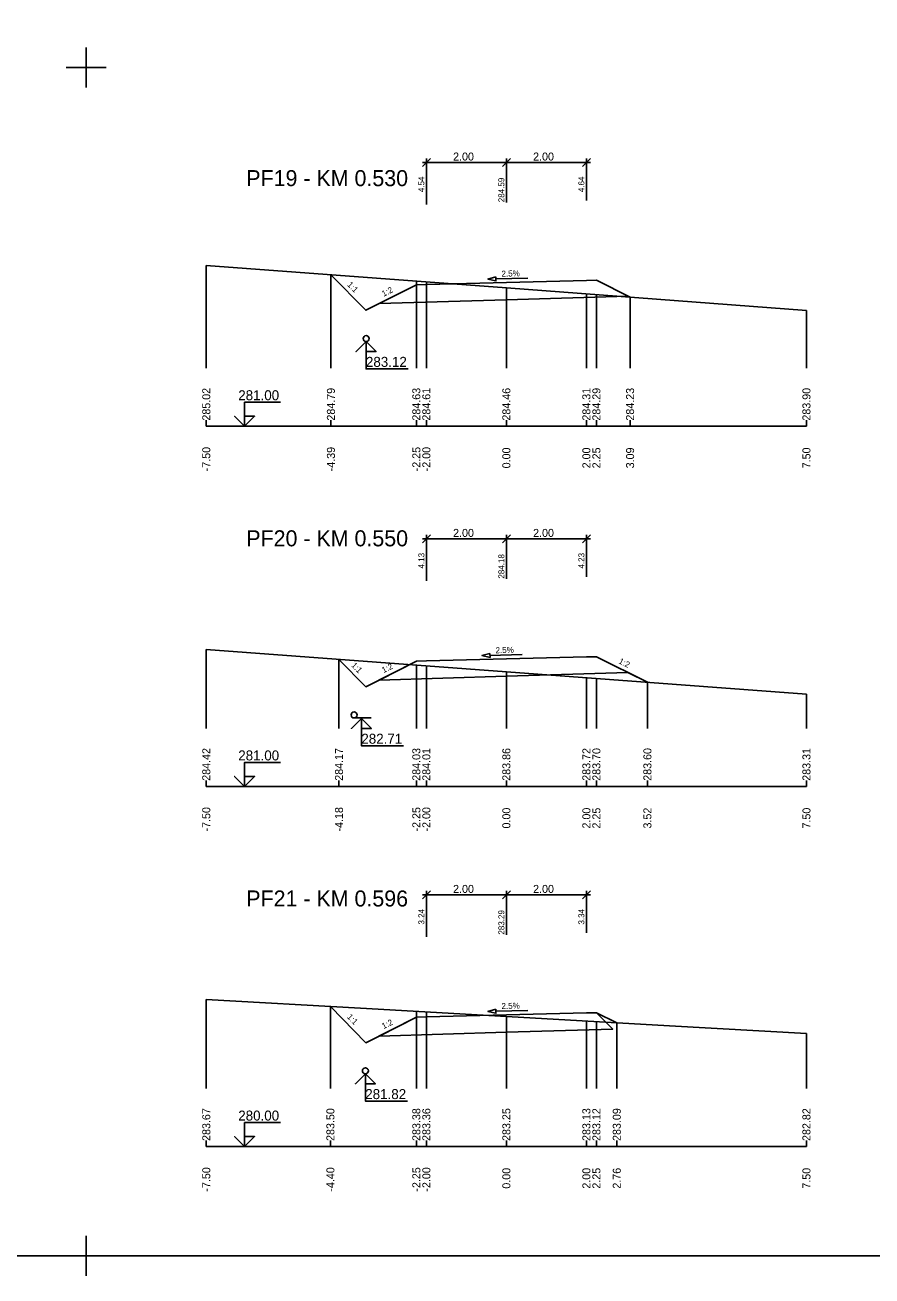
# Model space of a CAD drawing. Extents: x -5 to 1895, y -2 to 602.
# Drawn here: x 1244.7 to 1456.4, y -2.3 to 310.3 of the extents above; entities that cross this region are included whole.
import ezdxf

# ---------------------------------------------------------------- set-up
doc = ezdxf.new("R2010")
doc.units = 0
for name, color, linetype in [('KOTA', 7, 'Continuous'), ('KOTA_DELKY', 7, 'Continuous'), ('KOTA_DELKY_CONT', 7, 'Continuous'), ('KRIZENI', 7, 'Continuous'), ('NS_TELESO_VOZOVKY', 7, 'Continuous'), ('NS_V_PF', 7, 'Continuous'), ('REZY_PF_PUVODNI', 7, 'Continuous'), ('SESTAVY_REZU_PF', 7, 'Continuous'), ('SKLON', 7, 'Continuous'), ('SVK', 7, 'Continuous')]:
    doc.layers.add(name, color=color, linetype=linetype)

msp = doc.modelspace()

# ---------------------------------------------------------------- linework, layer by layer
for p, q in [((1260, 304.67), (1260, 294.67)), ((1260, 304.67), (1260, 294.67)), ((1260, 304.67), (1260, 294.67)), ((1260, 304.67), (1260, 294.67)), ((1260, 304.67), (1260, 294.67)), ((1260, 304.67), (1260, 294.67)), ((1260, 304.67), (1260, 294.67)), ((1260, 304.67), (1260, 294.67)), ((1260, 304.67), (1260, 294.67)), ((1260, 304.67), (1260, 294.67)), ((1260, 304.67), (1260, 294.67)), ((1260, 304.67), (1260, 294.67)), ((1260, 304.67), (1260, 294.67)), ((1260, 304.67), (1260, 294.67)), ((1260, 304.67), (1260, 294.67)), ((1260, 304.67), (1260, 294.67)), ((1260, 304.67), (1260, 294.67)), ((1260, 304.67), (1260, 294.67)), ((1260, 304.67), (1260, 294.67)), ((1260, 304.67), (1260, 294.67)), ((1260, 304.67), (1260, 294.67)), ((1260, 304.67), (1260, 294.67)), ((1260, 304.67), (1260, 294.67)), ((1260, 304.67), (1260, 294.67)), ((1260, 304.67), (1260, 294.67)), ((1260, 304.67), (1260, 294.67)), ((1260, 304.67), (1260, 294.67)), ((1260, 304.67), (1260, 294.67)), ((1260, 304.67), (1260, 294.67)), ((1260, 304.67), (1260, 294.67)), ((1260, 304.67), (1260, 294.67)), ((1260, 304.67), (1260, 294.67)), ((1260, 304.67), (1260, 294.67)), ((1260, 304.67), (1260, 294.67)), ((1260, 304.67), (1260, 294.67)), ((1260, 304.67), (1260, 294.67)), ((1260, 304.67), (1260, 294.67)), ((1260, 304.67), (1260, 294.67)), ((1260, 304.67), (1260, 294.67)), ((1260, 304.67), (1260, 294.67)), ((1260, 304.67), (1260, 294.67)), ((1260, 304.67), (1260, 294.67)), ((1260, 304.67), (1260, 294.67)), ((1260, 304.67), (1260, 294.67)), ((1260, 304.67), (1260, 294.67)), ((1260, 304.67), (1260, 294.67)), ((1260, 304.67), (1260, 294.67)), ((1260, 304.67), (1260, 294.67)), ((1260, 304.67), (1260, 294.67)), ((1260, 304.67), (1260, 294.67)), ((1260, 304.67), (1260, 294.67)), ((1260, 304.67), (1260, 294.67)), ((1260, 304.67), (1260, 294.67)), ((1260, 304.67), (1260, 294.67)), ((1265, 299.67), (1255, 299.67)), ((1265, 299.67), (1255, 299.67)), ((1265, 299.67), (1255, 299.67)), ((1265, 299.67), (1255, 299.67)), ((1265, 299.67), (1255, 299.67)), ((1265, 299.67), (1255, 299.67)), ((1265, 299.67), (1255, 299.67)), ((1265, 299.67), (1255, 299.67)), ((1265, 299.67), (1255, 299.67)), ((1265, 299.67), (1255, 299.67)), ((1265, 299.67), (1255, 299.67)), ((1265, 299.67), (1255, 299.67)), ((1265, 299.67), (1255, 299.67)), ((1265, 299.67), (1255, 299.67)), ((1265, 299.67), (1255, 299.67)), ((1265, 299.67), (1255, 299.67)), ((1265, 299.67), (1255, 299.67)), ((1265, 299.67), (1255, 299.67)), ((1265, 299.67), (1255, 299.67)), ((1265, 299.67), (1255, 299.67)), ((1265, 299.67), (1255, 299.67)), ((1265, 299.67), (1255, 299.67)), ((1265, 299.67), (1255, 299.67)), ((1265, 299.67), (1255, 299.67)), ((1265, 299.67), (1255, 299.67)), ((1265, 299.67), (1255, 299.67)), ((1265, 299.67), (1255, 299.67)), ((1265, 299.67), (1255, 299.67)), ((1265, 299.67), (1255, 299.67)), ((1265, 299.67), (1255, 299.67)), ((1265, 299.67), (1255, 299.67)), ((1265, 299.67), (1255, 299.67)), ((1265, 299.67), (1255, 299.67)), ((1265, 299.67), (1255, 299.67)), ((1265, 299.67), (1255, 299.67)), ((1265, 299.67), (1255, 299.67)), ((1265, 299.67), (1255, 299.67)), ((1265, 299.67), (1255, 299.67)), ((1265, 299.67), (1255, 299.67)), ((1265, 299.67), (1255, 299.67)), ((1265, 299.67), (1255, 299.67)), ((1265, 299.67), (1255, 299.67)), ((1265, 299.67), (1255, 299.67)), ((1265, 299.67), (1255, 299.67)), ((1265, 299.67), (1255, 299.67)), ((1265, 299.67), (1255, 299.67)), ((1265, 299.67), (1255, 299.67)), ((1265, 299.67), (1255, 299.67)), ((1265, 299.67), (1255, 299.67)), ((1265, 299.67), (1255, 299.67)), ((1265, 299.67), (1255, 299.67)), ((1265, 299.67), (1255, 299.67)), ((1265, 299.67), (1255, 299.67)), ((1265, 299.67), (1255, 299.67)), ((1260, 7.67), (1260, -2.33)), ((1260, 7.67), (1260, -2.33)), ((1260, 7.67), (1260, -2.33)), ((1260, 7.67), (1260, -2.33)), ((1260, 7.67), (1260, -2.33)), ((1260, 7.67), (1260, -2.33)), ((1260, 7.67), (1260, -2.33)), ((1260, 7.67), (1260, -2.33)), ((1260, 7.67), (1260, -2.33)), ((1260, 7.67), (1260, -2.33)), ((1260, 7.67), (1260, -2.33)), ((1260, 7.67), (1260, -2.33)), ((1265, 2.67), (1255, 2.67)), ((1265, 2.67), (1255, 2.67)), ((1265, 2.67), (1255, 2.67)), ((1265, 2.67), (1255, 2.67)), ((1265, 2.67), (1255, 2.67)), ((1265, 2.67), (1255, 2.67)), ((1265, 2.67), (1255, 2.67)), ((1265, 2.67), (1255, 2.67)), ((1265, 2.67), (1255, 2.67)), ((1265, 2.67), (1255, 2.67)), ((1265, 2.67), (1255, 2.67)), ((1265, 2.67), (1255, 2.67))]:
    msp.add_line(p, q)
msp.add_lwpolyline([(0, 596.67), (1890, 596.67), (1890, 2.67), (0, 2.67)], close=True)
at = {"layer": 'KOTA'}
for points in [[(1329.95, 231.16), (1327.45, 228.66), (1329.95, 231.16), (1329.95, 224.34), (1340.49, 224.34)], [(1329.95, 231.16), (1332.45, 228.66), (1329.95, 228.66), (1329.95, 231.16)], [(1329.95, 231.16), (1332.45, 228.66), (1329.95, 228.66)], [(1299.57, 210), (1297.07, 212.5), (1299.57, 210), (1299.57, 216), (1308.57, 216)], [(1299.57, 210), (1302.07, 212.5), (1299.57, 212.5), (1299.57, 210)], [(1299.57, 210), (1302.07, 212.5), (1299.57, 212.5)], [(1328.79, 136.99), (1326.29, 134.49), (1328.79, 136.99), (1328.79, 130.17), (1339.33, 130.17)], [(1326.95, 137.11), (1331.22, 137.11)], [(1328.79, 136.99), (1331.29, 134.49), (1328.79, 134.49), (1328.79, 136.99)], [(1328.79, 136.99), (1331.29, 134.49), (1328.79, 134.49)], [(1299.57, 120), (1297.07, 122.5), (1299.57, 120), (1299.57, 126), (1308.57, 126)], [(1299.57, 120), (1302.07, 122.5), (1299.57, 122.5), (1299.57, 120)], [(1299.57, 120), (1302.07, 122.5), (1299.57, 122.5)], [(1329.77, 48.19), (1327.27, 45.69), (1329.77, 48.19), (1329.77, 41.37), (1340.31, 41.37)], [(1329.77, 48.19), (1332.27, 45.69), (1329.77, 45.69), (1329.77, 48.19)], [(1329.77, 48.19), (1332.27, 45.69), (1329.77, 45.69)], [(1299.57, 30), (1297.07, 32.5), (1299.57, 30), (1299.57, 36), (1308.57, 36)], [(1299.57, 30), (1302.07, 32.5), (1299.57, 32.5), (1299.57, 30)], [(1299.57, 30), (1302.07, 32.5), (1299.57, 32.5)]]:
    msp.add_lwpolyline(points, dxfattribs=at)
at = {"layer": 'KOTA_DELKY'}
for points in [[(1344, 274.9), (1346, 276.9)], [(1344, 275.9), (1366, 275.9)], [(1345, 265.4), (1345, 276.9)], [(1364, 274.9), (1366, 276.9)], [(1364, 274.9), (1366, 276.9)], [(1364, 275.9), (1386, 275.9)], [(1365, 265.9), (1365, 276.9)], [(1365, 265.9), (1365, 276.9)], [(1384, 274.9), (1386, 276.9)], [(1385, 266.4), (1385, 276.9)], [(1344, 180.85), (1346, 182.85)], [(1344, 181.85), (1366, 181.85)], [(1345, 171.35), (1345, 182.85)], [(1364, 180.85), (1366, 182.85)], [(1364, 180.85), (1366, 182.85)], [(1364, 181.85), (1386, 181.85)], [(1365, 171.85), (1365, 182.85)], [(1365, 171.85), (1365, 182.85)], [(1384, 180.85), (1386, 182.85)], [(1385, 172.35), (1385, 182.85)], [(1344, 91.89), (1346, 93.89)], [(1345, 82.39), (1345, 93.89)], [(1364, 91.89), (1366, 93.89)], [(1364, 91.89), (1366, 93.89)], [(1365, 82.89), (1365, 93.89)], [(1365, 82.89), (1365, 93.89)], [(1384, 91.89), (1386, 93.89)], [(1385, 83.39), (1385, 93.89)], [(1344, 92.89), (1366, 92.89)], [(1364, 92.89), (1386, 92.89)]]:
    msp.add_lwpolyline(points, dxfattribs=at)
at = {"layer": 'KRIZENI'}
for centre in [(1329.95, 231.91), (1326.95, 137.86), (1329.77, 48.94)]:
    msp.add_circle(centre, 0.75, dxfattribs=at)
at = {"layer": 'NS_TELESO_VOZOVKY'}
for points in [[(1365, 245.9), (1385, 246.4), (1387.5, 246.47), (1395.92, 242.26), (1395.4, 242.52), (1365, 241.6), (1333.2, 240.65), (1342.5, 245.34), (1345, 245.4), (1365, 245.9)], [(1365, 151.85), (1385, 152.35), (1387.5, 152.41), (1400.25, 146.04), (1395.4, 148.46), (1365, 147.55), (1333.2, 146.59), (1342.5, 151.28), (1345, 151.35), (1365, 151.85)], [(1365, 62.89), (1385, 63.39), (1387.5, 63.45), (1391.57, 59.38), (1365, 58.59), (1333.2, 57.63), (1342.5, 62.32), (1345, 62.39), (1365, 62.89)]]:
    msp.add_lwpolyline(points, dxfattribs=at)
at = {"layer": 'NS_V_PF'}
for points in [[(1321.15, 247.86), (1329.87, 238.97), (1342.5, 245.34), (1345, 245.4), (1365, 245.9), (1385, 246.4), (1387.5, 246.47), (1395.92, 242.26)], [(1323.17, 151.74), (1329.87, 144.91), (1342.5, 151.28), (1345, 151.35), (1365, 151.85), (1385, 152.35), (1387.5, 152.41), (1400.25, 146.04)], [(1321.02, 64.97), (1329.87, 55.95), (1342.5, 62.32), (1345, 62.39), (1365, 62.89), (1385, 63.39), (1387.5, 63.45), (1392.59, 60.91)]]:
    msp.add_lwpolyline(points, dxfattribs=at)
at = {"layer": 'REZY_PF_PUVODNI'}
for points in [[(1290, 250.2), (1365, 244.58), (1365, 244.58), (1440, 238.95)], [(1290, 154.2), (1365, 148.65), (1440, 143.09)], [(1290, 66.73), (1328.55, 64.55), (1365, 62.48), (1405.74, 60.16), (1440, 58.22)]]:
    msp.add_lwpolyline(points, dxfattribs=at)
at = {"layer": 'SESTAVY_REZU_PF'}
for points in [[(1290, 210), (1440, 210)], [(1290, 120), (1440, 120)], [(1290, 30), (1440, 30)]]:
    msp.add_lwpolyline(points, dxfattribs=at)
at = {"layer": 'SKLON'}
for points in [[(1362.39, 247.34), (1360.4, 246.79), (1362.41, 246.34), (1362.39, 247.34)], [(1362.4, 246.84), (1370.4, 247.04)], [(1360.9, 153.24), (1358.91, 152.69), (1360.92, 152.24), (1360.9, 153.24)], [(1360.91, 152.74), (1368.91, 152.94)], [(1362.39, 64.32), (1360.4, 63.77), (1362.41, 63.32), (1362.39, 64.32)], [(1362.4, 63.82), (1370.4, 64.02)]]:
    msp.add_lwpolyline(points, dxfattribs=at)
for points in [[(1362.39, 247.34), (1360.4, 246.79), (1362.41, 246.34)], [(1360.9, 153.24), (1358.91, 152.69), (1360.92, 152.24)], [(1362.39, 64.32), (1360.4, 63.77), (1362.41, 63.32)]]:
    msp.add_lwpolyline(points, close=True, dxfattribs=at)
at = {"layer": 'SVK'}
for points in [[(1290, 224.5), (1290, 250.2)], [(1321.15, 224.5), (1321.15, 247.86)], [(1342.5, 224.5), (1342.5, 246.26)], [(1345, 224.5), (1345, 246.08)], [(1365, 224.5), (1365, 244.58)], [(1385, 224.5), (1385, 243.08)], [(1387.5, 224.5), (1387.5, 242.89)], [(1395.92, 224.5), (1395.92, 242.26)], [(1440, 224.5), (1440, 238.95)], [(1290, 210), (1290, 211.5)], [(1321.15, 210), (1321.15, 211.5)], [(1342.5, 210), (1342.5, 211.5)], [(1345, 210), (1345, 211.5)], [(1365, 210), (1365, 211.5)], [(1385, 210), (1385, 211.5)], [(1387.5, 210), (1387.5, 211.5)], [(1395.92, 210), (1395.92, 211.5)], [(1440, 210), (1440, 211.5)], [(1290, 134.5), (1290, 154.2)], [(1323.17, 134.5), (1323.17, 151.74)], [(1342.5, 134.5), (1342.5, 150.31)], [(1345, 134.5), (1345, 150.13)], [(1365, 134.5), (1365, 148.65)], [(1385, 134.5), (1385, 147.16)], [(1387.5, 134.5), (1387.5, 146.98)], [(1400.25, 134.5), (1400.25, 146.04)], [(1440, 134.5), (1440, 143.09)], [(1290, 120), (1290, 121.5)], [(1323.17, 120), (1323.17, 121.5)], [(1342.5, 120), (1342.5, 121.5)], [(1345, 120), (1345, 121.5)], [(1365, 120), (1365, 121.5)], [(1385, 120), (1385, 121.5)], [(1387.5, 120), (1387.5, 121.5)], [(1400.25, 120), (1400.25, 121.5)], [(1440, 120), (1440, 121.5)], [(1290, 44.5), (1290, 66.73)], [(1321.02, 44.5), (1321.02, 64.97)], [(1342.5, 44.5), (1342.5, 63.76)], [(1345, 44.5), (1345, 63.61)], [(1365, 44.5), (1365, 62.48)], [(1385, 44.5), (1385, 61.34)], [(1387.5, 44.5), (1387.5, 61.19)], [(1392.59, 44.5), (1392.59, 60.91)], [(1440, 44.5), (1440, 58.22)], [(1290, 30), (1290, 31.5)], [(1321.02, 30), (1321.02, 31.5)], [(1342.5, 30), (1342.5, 31.5)], [(1345, 30), (1345, 31.5)], [(1365, 30), (1365, 31.5)], [(1385, 30), (1385, 31.5)], [(1387.5, 30), (1387.5, 31.5)], [(1392.59, 30), (1392.59, 31.5)], [(1440, 30), (1440, 31.5)]]:
    msp.add_lwpolyline(points, dxfattribs=at)

# ---------------------------------------------------------------- texts
at = {"layer": 'KOTA'}
for s, p in [('283.12', (1329.9, 224.84)), ('281.00', (1297.99, 216.5)), ('282.71', (1328.75, 130.67)), ('281.00', (1297.99, 126.5)), ('281.82', (1329.73, 41.87)), ('280.00', (1297.99, 36.5))]:
    msp.add_text(s, height=2.5, dxfattribs=at).set_placement(p)
at = {"layer": 'KOTA_DELKY'}
for p in [(1351.69, 276.4), (1371.69, 276.4), (1351.69, 182.35), (1371.69, 182.35), (1351.69, 93.39), (1371.69, 93.39)]:
    msp.add_text('2.00', height=2, dxfattribs=at).set_placement(p)
at = {"layer": 'KOTA_DELKY_CONT'}
for s, p in [('4.54', (1344.5, 268.49)), ('284.59', (1364.5, 265.98)), ('4.64', (1384.5, 268.49)), ('4.13', (1344.5, 174.44)), ('4.23', (1384.5, 174.44)), ('284.18', (1364.5, 171.92)), ('3.24', (1344.5, 85.48)), ('283.29', (1364.5, 82.96)), ('3.34', (1384.5, 85.48))]:
    msp.add_text(s, height=1.5, rotation=90, dxfattribs=at).set_placement(p)
at = {"layer": 'SESTAVY_REZU_PF'}
for s, p in [('PF19 - KM 0.530', (1300, 270)), ('PF20 - KM 0.550', (1300, 180)), ('PF21 - KM 0.596', (1300, 90))]:
    msp.add_text(s, height=4, dxfattribs=at).set_placement(p)
at = {"layer": 'SKLON'}
for s, rotation, p in [('2.5%', 1.4321, (1363.8, 247.37)), ('1:1', 314.4213, (1325.12, 245.24)), ('1:2', 26.7649, (1334.32, 242.34)), ('2.5%', 1.4321, (1362.31, 153.28)), ('1:1', 314.4213, (1326.13, 150.15)), ('1:2', 26.7649, (1334.32, 148.28)), ('1:2', 333.4349, (1392.91, 150.82)), ('2.5%', 1.4321, (1363.8, 64.36)), ('1:1', 314.4213, (1325.05, 62.29)), ('1:2', 26.7649, (1334.32, 59.32))]:
    msp.add_text(s, height=1.5, rotation=rotation, dxfattribs=at).set_placement(p)
at = {"layer": 'SVK'}
for s, p in [(' 285.02', (1291, 210.67)), (' 284.79', (1322.15, 210.67)), (' 284.63', (1343.5, 210.67)), (' 284.61', (1346, 210.67)), (' 284.46', (1366, 210.67)), (' 284.31', (1386, 210.67)), (' 284.29', (1388.5, 210.67)), (' 284.23', (1396.92, 210.67)), (' 283.90', (1441, 210.67)), (' -7.50', (1291, 198)), (' -4.39', (1322.15, 198)), (' -2.25', (1343.5, 198)), (' -2.00', (1346, 198)), ('  0.00', (1366, 198)), ('  2.00', (1386, 198)), ('  2.25', (1388.5, 198)), ('  3.09', (1396.92, 198)), ('  7.50', (1441, 198)), (' 284.42', (1291, 120.67)), (' 284.17', (1324.17, 120.67)), (' 284.03', (1343.5, 120.67)), (' 284.01', (1346, 120.67)), (' 283.86', (1366, 120.67)), (' 283.72', (1386, 120.67)), (' 283.70', (1388.5, 120.67)), (' 283.60', (1401.25, 120.67)), (' 283.31', (1441, 120.67)), (' -7.50', (1291, 108)), (' -4.18', (1324.17, 108)), (' -2.25', (1343.5, 108)), (' -2.00', (1346, 108)), ('  0.00', (1366, 108)), ('  2.00', (1386, 108)), ('  2.25', (1388.5, 108)), ('  3.52', (1401.25, 108)), ('  7.50', (1441, 108)), (' 283.67', (1291, 30.67)), (' 283.50', (1322.02, 30.67)), (' 283.38', (1343.5, 30.67)), (' 283.36', (1346, 30.67)), (' 283.25', (1366, 30.67)), (' 283.13', (1386, 30.67)), (' 283.12', (1388.5, 30.67)), (' 283.09', (1393.59, 30.67)), (' 282.82', (1441, 30.67)), (' -7.50', (1291, 18)), (' -4.40', (1322.02, 18)), (' -2.25', (1343.5, 18)), (' -2.00', (1346, 18)), ('  0.00', (1366, 18)), ('  2.00', (1386, 18)), ('  2.25', (1388.5, 18)), ('  2.76', (1393.59, 18)), ('  7.50', (1441, 18))]:
    msp.add_text(s, height=2, rotation=90, dxfattribs=at).set_placement(p)

doc.saveas('drawing.dxf')
